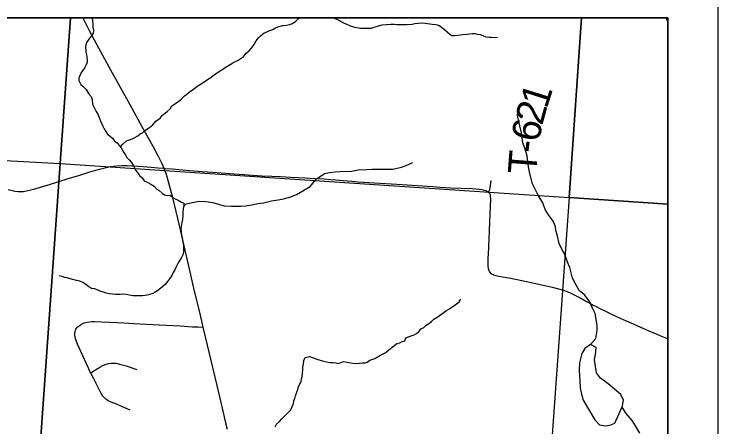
# Model space of a CAD drawing. Extents: x -8.2 to 34, y 0 to 22.
# Drawn here: x 7.595 to 9, y 20.084 to 20.907 of the extents above; entities that cross this region are included whole.
import ezdxf

# ---------------------------------------------------------------- set-up
doc = ezdxf.new("R2010")
doc.units = 0
for name, color, linetype in [('GM_X_Corporation', 7, 'Continuous'), ('GM_X_Minor_River', 7, 'Continuous'), ('GM_X_State_Route', 7, 'Continuous'), ('GM_X_Township_Road', 7, 'Continuous'), ('GM_X_Township_Road_Text', 7, 'Continuous'), ('SH_Data', 7, 'Continuous')]:
    doc.layers.add(name, color=color, linetype=linetype)

msp = doc.modelspace()

# ---------------------------------------------------------------- linework, layer by layer
at = {"layer": 'GM_X_Corporation'}
for points in [[(7.7078, 20.9), (6.6786, 20.9), (6.6629, 20.6653), (7.6877, 20.6096)], [(8.7279, 20.9), (7.7078, 20.9), (7.6877, 20.6096), (8.7029, 20.5419)], [(8.9, 20.5285), (8.9, 20.9), (8.7279, 20.9), (8.7029, 20.5419)], [(6.6629, 20.6653), (7.6877, 20.6096), (7.6147, 19.5864), (6.5914, 19.6487)], [(7.6877, 20.6096), (8.7029, 20.5419), (8.6299, 19.5206), (7.6147, 19.5864)], [(8.9, 19.5025), (8.9, 20.5285), (8.7029, 20.5419), (8.6299, 19.5206)]]:
    msp.add_lwpolyline(points, close=True, dxfattribs=at)
at = {"layer": 'GM_X_Minor_River'}
for points in [[(7.7513, 20.9), (7.7521, 20.8936), (7.7525, 20.8871), (7.7529, 20.8811), (7.7538, 20.8746), (7.7534, 20.8693)], [(7.8079, 20.6424), (7.8127, 20.6479), (7.8198, 20.6548), (7.8259, 20.6564), (7.8308, 20.6584), (7.8353, 20.6607), (7.8425, 20.6649), (7.847, 20.6688), (7.8515, 20.6707), (7.8564, 20.6749), (7.8659, 20.6815), (7.8726, 20.6865), (7.8783, 20.6938), (7.8873, 20.6999), (7.891, 20.7053), (7.9012, 20.7134), (7.9068, 20.7187), (7.9102, 20.7241), (7.9238, 20.7333), (7.9286, 20.7376), (7.9358, 20.7441), (7.9403, 20.7475), (7.9452, 20.7514), (7.9535, 20.7579), (7.961, 20.7637), (7.9689, 20.7683), (7.9814, 20.7768), (7.9878, 20.7811), (7.9934, 20.7857), (8.001, 20.7899), (8.0085, 20.7957), (8.0198, 20.8026), (8.0266, 20.8065), (8.0319, 20.8104), (8.0428, 20.8154), (8.0485, 20.8193), (8.053, 20.822), (8.0579, 20.8288), (8.0646, 20.8338), (8.0688, 20.8388), (8.0744, 20.8465), (8.0789, 20.8537), (8.0833, 20.8599), (8.0879, 20.8648), (8.0939, 20.8691), (8.0984, 20.871), (8.1041, 20.8737), (8.1116, 20.8768), (8.1169, 20.8799), (8.1218, 20.8819), (8.132, 20.8846), (8.1389, 20.8851), (8.1449, 20.8863), (8.151, 20.8886), (8.1574, 20.8929), (8.1623, 20.8975), (8.1666, 20.9)], [(8.233, 20.9), (8.2344, 20.8993), (8.2393, 20.8974), (8.2515, 20.8907), (8.2634, 20.8855), (8.2679, 20.8833), (8.2752, 20.8814), (8.2866, 20.8793), (8.293, 20.8789), (8.3014, 20.879), (8.3078, 20.8795), (8.3143, 20.881), (8.3226, 20.8838), (8.3301, 20.8857), (8.3377, 20.8866), (8.3476, 20.8874), (8.3544, 20.8871), (8.359, 20.8868), (8.3673, 20.8865), (8.3791, 20.8866), (8.3897, 20.8874), (8.3954, 20.8883), (8.4018, 20.8891), (8.4109, 20.8899), (8.425, 20.8878), (8.4299, 20.8871), (8.4368, 20.8864), (8.4444, 20.8842), (8.449, 20.8808), (8.4547, 20.8767), (8.4597, 20.8718), (8.4647, 20.8673), (8.4693, 20.8646), (8.4753, 20.8647), (8.481, 20.8655), (8.486, 20.8659), (8.4905, 20.8664), (8.4992, 20.8672), (8.5049, 20.868), (8.5095, 20.8688), (8.5148, 20.8685), (8.5197, 20.8674), (8.5258, 20.8663), (8.5308, 20.8648), (8.5372, 20.8619), (8.5437, 20.8612), (8.5482, 20.8612), (8.5536, 20.8609), (8.5604, 20.8613)], [(8.9, 20.8917), (8.8986, 20.8945), (8.8967, 20.9)], [(7.7534, 20.8693), (7.7497, 20.8639), (7.746, 20.8593), (7.7422, 20.8536), (7.7392, 20.8486), (7.7378, 20.8429), (7.7387, 20.8323), (7.7402, 20.827), (7.7411, 20.8164), (7.7411, 20.8118), (7.7397, 20.8072), (7.7367, 20.8011), (7.7318, 20.7942), (7.7289, 20.7893), (7.7248, 20.7797), (7.7248, 20.7752), (7.7287, 20.7672), (7.7333, 20.7631), (7.7394, 20.7571), (7.7441, 20.7491), (7.7495, 20.7427), (7.751, 20.737), (7.7523, 20.7279), (7.7569, 20.7181), (7.7596, 20.7132), (7.7627, 20.7075), (7.7651, 20.7014), (7.7674, 20.6961), (7.7697, 20.6901), (7.7725, 20.684), (7.7752, 20.6784), (7.7783, 20.6731), (7.7821, 20.6682), (7.7871, 20.6636), (7.7925, 20.6591), (7.7959, 20.6542), (7.8009, 20.6509), (7.8047, 20.6463), (7.8094, 20.6407), (7.8144, 20.6316), (7.8175, 20.6263), (7.8206, 20.6214), (7.8252, 20.6169), (7.8294, 20.6124), (7.8329, 20.6059), (7.8356, 20.6006), (7.8379, 20.5961), (7.8421, 20.5916), (7.846, 20.5855), (7.8514, 20.5806), (7.8552, 20.575), (7.8621, 20.5716), (7.8682, 20.5683), (7.8747, 20.5641), (7.8804, 20.5585), (7.885, 20.5555), (7.8908, 20.5502), (7.8957, 20.5469), (7.9007, 20.5458), (7.9071, 20.5462), (7.9125, 20.5417), (7.9171, 20.5391), (7.9228, 20.5361), (7.9293, 20.5324), (7.9339, 20.5301), (7.9339, 20.5244), (7.9332, 20.5195), (7.9325, 20.5119), (7.9322, 20.5058), (7.9315, 20.4978), (7.9305, 20.4917), (7.929, 20.4841), (7.9283, 20.4784), (7.9288, 20.4727), (7.9296, 20.467), (7.9308, 20.4621), (7.9316, 20.4552), (7.9328, 20.4499), (7.9333, 20.4431), (7.9337, 20.4374), (7.9334, 20.4321), (7.9323, 20.4271), (7.9289, 20.421), (7.9248, 20.4149), (7.9222, 20.4099), (7.9192, 20.4034), (7.9163, 20.3977), (7.9129, 20.392), (7.9103, 20.3863), (7.9058, 20.3798), (7.9017, 20.374), (7.8972, 20.3683), (7.8886, 20.3606), (7.8822, 20.356), (7.8773, 20.3529), (7.8724, 20.3502), (7.8637, 20.3478), (7.8568, 20.3466), (7.8515, 20.3458), (7.8447, 20.3454), (7.8383, 20.3457)], [(8.7455, 20.2484), (8.7561, 20.2605), (8.7593, 20.2764), (8.7587, 20.2863), (8.757, 20.2992), (8.7553, 20.3103), (8.7491, 20.3226), (8.745, 20.3325), (8.7346, 20.3467), (8.723, 20.3564), (8.7153, 20.371), (8.7101, 20.3806), (8.7048, 20.4019), (8.6996, 20.4127), (8.6949, 20.4264), (8.6883, 20.4387), (8.6831, 20.4498), (8.6796, 20.4643), (8.6774, 20.4738), (8.675, 20.4849), (8.6709, 20.4944), (8.6617, 20.5071), (8.6554, 20.5175), (8.6507, 20.5313), (8.6414, 20.5462), (8.63, 20.5688), (8.6246, 20.5894), (8.6222, 20.6028), (8.6191, 20.6249), (8.6144, 20.6401), (8.6108, 20.6505), (8.6081, 20.6706), (8.6049, 20.6844), (8.6024, 20.6939), (8.5992, 20.7073)], [(7.9341, 20.5265), (7.9339, 20.5244), (7.9386, 20.5287), (7.9485, 20.5308), (7.9649, 20.5343), (7.9782, 20.5337), (7.9922, 20.532), (8.0035, 20.5284), (8.0148, 20.5252), (8.0292, 20.5242), (8.0478, 20.5246), (8.0573, 20.5252), (8.0702, 20.5269), (8.0824, 20.5294), (8.0934, 20.5307), (8.1094, 20.535), (8.1224, 20.5371), (8.1334, 20.5388), (8.1479, 20.5428), (8.1589, 20.5475), (8.1716, 20.5549), (8.1861, 20.5634), (8.1985, 20.5781), (8.2146, 20.5896), (8.2249, 20.5917), (8.2363, 20.593), (8.2469, 20.5936), (8.2689, 20.5944), (8.2822, 20.5965), (8.2986, 20.5977), (8.3099, 20.5979), (8.3384, 20.5979), (8.3513, 20.598), (8.3684, 20.6023), (8.3795, 20.6063), (8.3909, 20.6114)], [(7.8383, 20.3457), (7.8329, 20.3456), (7.8253, 20.3471), (7.8193, 20.3482), (7.8124, 20.3489), (7.8063, 20.3484), (7.7976, 20.3483), (7.7919, 20.349), (7.7858, 20.3497), (7.7794, 20.3512), (7.774, 20.353), (7.7676, 20.3549), (7.7626, 20.3571), (7.7565, 20.3593), (7.7508, 20.3604), (7.7447, 20.3634), (7.7386, 20.3679), (7.7329, 20.372), (7.7264, 20.3746), (7.7199, 20.3765), (7.7119, 20.3783), (7.7013, 20.3812), (7.6967, 20.3823), (7.6914, 20.3842), (7.6856, 20.3857)], [(8.1162, 20.0842), (8.1191, 20.0895), (8.1248, 20.0953), (8.1296, 20.1007), (8.1342, 20.1049), (8.139, 20.1099), (8.1439, 20.1141), (8.1477, 20.1187), (8.1506, 20.1248), (8.1529, 20.1309), (8.1536, 20.1362), (8.1554, 20.1408), (8.1572, 20.1465), (8.1598, 20.1538), (8.1617, 20.1599), (8.1631, 20.1644), (8.1657, 20.1702), (8.1683, 20.1747), (8.169, 20.1801), (8.1701, 20.1846), (8.1715, 20.1976), (8.1718, 20.2033), (8.1729, 20.2094), (8.174, 20.2166), (8.1762, 20.2227), (8.1853, 20.2247), (8.191, 20.2228), (8.1994, 20.2195), (8.2062, 20.2177), (8.2108, 20.2162), (8.2192, 20.214), (8.2264, 20.2129), (8.2317, 20.2126), (8.2374, 20.2119), (8.242, 20.2108), (8.2465, 20.212), (8.2529, 20.2147), (8.2602, 20.2132), (8.2678, 20.2118), (8.2761, 20.2107), (8.2848, 20.2116), (8.2909, 20.2124), (8.2958, 20.2124), (8.3004, 20.2132), (8.3057, 20.2171), (8.3155, 20.2206), (8.3264, 20.2275), (8.3359, 20.2322), (8.3426, 20.2372), (8.3498, 20.243), (8.3547, 20.2468), (8.3592, 20.2503), (8.3653, 20.2522), (8.3702, 20.2545), (8.3751, 20.2561), (8.3773, 20.2618), (8.386, 20.2653), (8.3936, 20.2681), (8.3988, 20.2704), (8.4041, 20.275), (8.4075, 20.2796), (8.4131, 20.2827), (8.418, 20.2873), (8.4229, 20.2904), (8.4282, 20.2946), (8.4331, 20.2992), (8.4399, 20.3031), (8.4444, 20.3065), (8.4493, 20.31), (8.4587, 20.3166), (8.4632, 20.3193), (8.473, 20.3254), (8.4836, 20.3339), (8.4873, 20.3389)], [(8.844, 20.0716), (8.8355, 20.0862), (8.8288, 20.0973), (8.8169, 20.1112), (8.8091, 20.1238), (8.8116, 20.1375), (8.8061, 20.149), (8.7934, 20.1598), (8.7807, 20.1703), (8.7657, 20.1815), (8.7575, 20.1919), (8.7558, 20.2049), (8.7537, 20.219), (8.7554, 20.2288), (8.7568, 20.2429), (8.7455, 20.2484), (8.7347, 20.2409), (8.7285, 20.2308), (8.724, 20.2119), (8.723, 20.1978), (8.7236, 20.186), (8.7242, 20.1765), (8.7251, 20.1624), (8.7276, 20.1495), (8.7312, 20.1376), (8.7541, 20.0986)], [(8.7749, 20.0863), (8.7844, 20.0881), (8.7943, 20.0917), (8.8088, 20.1241)], [(8.7538, 20.0989), (8.7635, 20.0888), (8.7749, 20.0863)]]:
    msp.add_lwpolyline(points, dxfattribs=at)
at = {"layer": 'GM_X_State_Route'}
msp.add_lwpolyline([(7.7325, 20.9), (7.7382, 20.8889), (7.7455, 20.8746), (7.7554, 20.8559), (7.7679, 20.8329), (7.7882, 20.7959), (7.8262, 20.7268), (7.8383, 20.7051), (7.8513, 20.6817), (7.8716, 20.6454), (7.8831, 20.6241), (7.8905, 20.6091), (7.8946, 20.5998), (7.8952, 20.5983), (7.8988, 20.5885), (7.9032, 20.5736), (7.9109, 20.5442), (7.9183, 20.514), (7.9273, 20.4747), (7.934, 20.4456), (7.9439, 20.402), (7.955, 20.3548), (7.9645, 20.3156), (7.9722, 20.2833), (7.9808, 20.2472), (8.0003, 20.167), (8.0089, 20.1301), (8.0175, 20.0925), (8.0208, 20.0798)], dxfattribs=at)
at = {"layer": 'GM_X_Township_Road'}
for points in [[(7.5839, 20.5579), (7.5972, 20.5546), (7.6034, 20.5535), (7.6077, 20.5533), (7.6146, 20.5539), (7.6232, 20.5555), (7.6352, 20.5585), (7.668, 20.5685), (7.7033, 20.5794), (7.7247, 20.5856), (7.7447, 20.5919), (7.7636, 20.5976), (7.7768, 20.601), (7.7883, 20.6032), (7.7999, 20.6047), (7.811, 20.6054), (7.8209, 20.6055), (7.832, 20.6051), (7.8531, 20.6034), (7.8692, 20.602), (7.8828, 20.6008), (7.8946, 20.5998), (7.8977, 20.5996), (7.9107, 20.5985), (7.9465, 20.5956), (7.9707, 20.5937), (7.9923, 20.592), (8.0084, 20.5907), (8.0348, 20.5888), (8.0545, 20.5877), (8.0715, 20.5864), (8.0897, 20.5851), (8.1096, 20.5839), (8.1271, 20.5832), (8.1469, 20.5822), (8.163, 20.5815), (8.1766, 20.5808), (8.1964, 20.5798), (8.2138, 20.5788), (8.2274, 20.5776), (8.2366, 20.5768), (8.2599, 20.5747), (8.2698, 20.574), (8.2815, 20.5732), (8.315, 20.5711), (8.3591, 20.5684), (8.4006, 20.5656), (8.4204, 20.5642), (8.4309, 20.5634), (8.4457, 20.5624), (8.4667, 20.5612), (8.4878, 20.5602), (8.5094, 20.5593), (8.5242, 20.5581), (8.5288, 20.5575), (8.5341, 20.5565), (8.5382, 20.5548), (8.5422, 20.5523), (8.5442, 20.5499), (8.5452, 20.5469), (8.5457, 20.5443), (8.5461, 20.5387), (8.5457, 20.525), (8.545, 20.507), (8.5445, 20.494), (8.5438, 20.4748), (8.5431, 20.4587), (8.5423, 20.4445), (8.5412, 20.4271), (8.541, 20.4228), (8.5406, 20.4122), (8.5409, 20.4048), (8.5418, 20.3999), (8.543, 20.3964), (8.5444, 20.3937), (8.5458, 20.3916), (8.5484, 20.3892), (8.552, 20.3875), (8.5568, 20.3859), (8.563, 20.3846), (8.5699, 20.3834), (8.5786, 20.3819), (8.5861, 20.3806), (8.5994, 20.378), (8.6428, 20.3686), (8.6693, 20.3627), (8.6817, 20.3599), (8.6919, 20.3572), (8.6993, 20.3546), (8.7076, 20.3506), (8.7147, 20.3468), (8.7311, 20.3381), (8.7379, 20.3343), (8.7441, 20.331), (8.7512, 20.3273), (8.7573, 20.3241), (8.7645, 20.3204), (8.7767, 20.3143), (8.786, 20.3095), (8.796, 20.3049), (8.8046, 20.3013), (8.8168, 20.2961), (8.8309, 20.2898), (8.8458, 20.2833), (8.8548, 20.2793), (8.8635, 20.2754), (8.8719, 20.2719), (8.8838, 20.2667), (8.8941, 20.2623), (8.9, 20.2598)], [(8.5422, 20.5523), (8.5433, 20.5541), (8.5449, 20.5574), (8.5458, 20.5606), (8.5465, 20.5654), (8.5473, 20.5753)], [(7.8274, 20.118), (7.8163, 20.1227), (7.7996, 20.1295), (7.7893, 20.1337), (7.7833, 20.1365), (7.7808, 20.138), (7.7787, 20.1394), (7.7751, 20.1428), (7.7728, 20.1454), (7.7712, 20.1479), (7.7685, 20.1525), (7.765, 20.159), (7.7544, 20.18), (7.75, 20.1888), (7.7484, 20.1921), (7.7469, 20.1949), (7.7437, 20.2016), (7.7287, 20.2347), (7.722, 20.2493), (7.7191, 20.2568), (7.7182, 20.2596), (7.7178, 20.2613), (7.7173, 20.2637), (7.717, 20.2656), (7.7168, 20.2672), (7.7168, 20.2688), (7.7167, 20.2705), (7.7169, 20.2725), (7.7172, 20.2744), (7.718, 20.2772), (7.719, 20.2793), (7.72, 20.2809), (7.7217, 20.2829), (7.7229, 20.284), (7.7262, 20.2868), (7.7299, 20.2891), (7.7329, 20.2904), (7.7356, 20.2915), (7.7385, 20.2924), (7.7417, 20.2931), (7.7468, 20.2938), (7.7508, 20.2942), (7.7559, 20.2945), (7.7701, 20.2941), (7.8005, 20.2924), (7.8148, 20.2916), (7.8346, 20.2904), (7.8725, 20.2884), (7.8991, 20.2871), (7.9276, 20.2856), (7.9512, 20.2841), (7.9624, 20.2836), (7.9722, 20.2833)], [(7.7484, 20.1921), (7.7544, 20.196), (7.7665, 20.2036), (7.7725, 20.2069), (7.7771, 20.2087), (7.7836, 20.2105), (7.7891, 20.2115), (7.7916, 20.2117), (7.7941, 20.2116), (7.799, 20.2111), (7.8057, 20.2097), (7.8194, 20.2058), (7.8402, 20.1986)]]:
    msp.add_lwpolyline(points, dxfattribs=at)
at = {"layer": 'SH_Data'}
for p, q in [((9, 21), (9, 14)), ((2.1, 20.9), (8.9, 20.9)), ((8.9, 20.9), (8.9, 14.1))]:
    msp.add_line(p, q, dxfattribs=at)

# ---------------------------------------------------------------- texts
at = {"layer": 'GM_X_Township_Road_Text'}
for s, rotation, p in [('1', 72.4992, (8.6583, 20.717)), ('2', 74.6892, (8.6492, 20.6838)), ('6', 79.0691, (8.6428, 20.6505)), ('-', 83.449, (8.6403, 20.6285)), ('T', 85.639, (8.6372, 20.5867))]:
    msp.add_text(s, height=0.0568, rotation=rotation, dxfattribs=at).set_placement(p)

doc.saveas('drawing.dxf')
